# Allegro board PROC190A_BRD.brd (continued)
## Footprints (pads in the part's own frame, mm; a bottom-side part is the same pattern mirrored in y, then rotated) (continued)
CON_MUSBB5_629105150521_S_R_S_2-7
  round 0.686 hole 0.813 unplated: (-2.5,1.848) (2.5,1.848)
  rect 0.457x1.295 smd: 1(-1.3,2.948) 2(-0.65,2.948) 3(0,2.948) 4(0.65,2.948) 5(1.3,2.948)
  oval 1.448x2.311 hole 0.864x1.727: 6(-3.725,2.898) 7(3.725,2.898)
  oval 1.143x1.803 hole 0.559x1.219: 8(-3.875,-0.902) 9(3.875,-0.902)
CON_SD9_MEM2052-00-195-00_S_R_S_2
  rect 0.787x1.499 smd: 1(1.94,-3.66) 2(0.84,-3.26) 3(-0.26,-3.66) 4(-1.36,-3.86) 5(-2.46,-3.66) 6(-3.56,-3.86) 7(-4.66,-3.66) 8(-5.76,-3.66)
  rect 0.991x0.94 smd: 9(-3.56,7.425)
  rect 1.397x1.905 smd: SH1(6.6,-6.95) SH2(-6.55,-5.95)
  rect 1.295x1.397 smd: SH3(0.75,7.2)
  rect 1.194x1.397 smd: SH4(-5.008,7.2)
CON_USBC24_2012670_S_R_S_3-9
  rect 0.305x0.762 smd: A1(-3,4.056) A2(-2.5,4.056) A3(-2,4.056) A4(-1.5,4.056) A5(-1,4.056) A6(-0.5,4.056) A7(0.5,4.056) A8(1,4.056) A9(1.5,4.056) A10(2,4.056) A11(2.5,4.056) A12(3,4.056) B2(2.25,2.356) B3(1.75,2.356) B4(1.25,2.356) B5(0.75,2.356) B6(0.25,2.356) B7(-0.25,2.356) B8(-0.75,2.356) B9(-1.25,2.356) B10(-1.75,2.356) B11(-2.25,2.356)
  rect 0.94x0.762 smd: B1(3.05,2.356) B12(-3.05,2.356)
  oval 1.194x2.21 hole 0.61x1.575: SH1(-4.32,3.246) SH2(4.32,3.246)
  oval 1.194x3.708 hole 0.61x2.083: SH3(4.62,-2.114) SH4(-4.62,-2.114)
DIO_DFN0201_0-4
  rect 0.229x0.381 smd: 1(-0.22,0) 2(0.22,0)
DIO_DFN0402_0-5
  rect 0.356x0.61 smd: 1(-0.34,0) 2(0.34,0)
DIO_SOT23_123
  rect 1.016x0.61 smd: 1(-1.15,0.95) 2(-1.15,-0.95) 3(1.15,0)
DIO_SOT323-3_1-1
  rect 0.838x0.457 smd: 1(-1.05,0.65) 2(-1.05,-0.65) 3(1.05,0)
DSBGA12_15-74_60X70_0-4
  round 0.279 smd: A1(-0.4,0.6) A2(0,0.6) A3(0.4,0.6) B1(-0.4,0.2) B2(0,0.2) B3(0.4,0.2) C1(-0.4,-0.2) C2(0,-0.2) C3(0.4,-0.2) D1(-0.4,-0.6) D2(0,-0.6) D3(0.4,-0.6)
EMIFIL_BLM15A_0402_0-6
  rect 0.61x0.61 smd: 1(-0.46,0) 2(0.46,0)
EMIFIL_BLM18K_0603
  rect 0.94x1.194 smd: 1(-0.825,0) 2(0.825,0)
EMIFIL_BLM18P_0603_0-8
  rect 0.991x0.991 smd: 1(-0.75,0) 2(0.75,0)
HDR_1X2_90120-0122_S_T_5-6
  rect 1.702x1.702 hole 1.016: 1(0,0)
  round 1.702 hole 1.016: 2(-2.54,0)
HDR_1X2_61300211121_S_T_8-6
  rect 1.803x1.803 hole 1.118: 1(0,0)
  round 1.803 hole 1.118: 2(-2.54,0)
HDR_1X3_100_S_T
  rect 1.803x1.803 hole 1.118: 1(0,0)
  round 1.803 hole 1.118: 2(-2.54,0) 3(-5.08,0)
HDR_1X3_87224-3_S_T_10-8
  rect 1.6x1.6 hole 0.914: 1(0,0)
  round 1.6 hole 0.914: 2(-2.54,0) 3(-5.08,0)
HDR_2X4_90131-07_S_T_9-5
  rect 1.702x1.702 hole 1.016: 1(0,0)
  round 1.702 hole 1.016: 2(0,2.54) 3(2.54,0) 4(2.54,2.54) 5(5.08,0) 6(5.08,2.54) 7(7.62,0) 8(7.62,2.54)
HDR_2X5_PEC05DAAN_S_T_8-6
  rect 1.702x1.702 hole 1.016: 1(0,0)
  round 1.702 hole 1.016: 2(0,2.54) 3(2.54,0) 4(2.54,2.54) 5(5.08,0) 6(5.08,2.54) 7(7.62,0) 8(7.62,2.54) 9(10.16,0) 10(10.16,2.54)
HDR_2X10_FTR-110-51-D-06_S_S_8-7
  rect 0.711x3.124 smd: 1(-5.715,-2.578) 2(-5.715,2.578) 3(-4.445,-2.578) 4(-4.445,2.578) 5(-3.175,-2.578) 7(-1.905,-2.578) 8(-1.905,2.578) 9(-0.635,-2.578) 10(-0.635,2.578) 11(0.635,-2.578) 12(0.635,2.578) 13(1.905,-2.578) 14(1.905,2.578) 15(3.175,-2.578) 16(3.175,2.578) 17(4.445,-2.578) 18(4.445,2.578) 19(5.715,-2.578) 20(5.715,2.578)
HDR_6X2_61301221121_P_S_T_8-6
  rect 1.803x1.803 hole 1.118: 1(0,0)
  round 1.803 hole 1.118: 2(0,2.54) 3(2.54,0) 4(2.54,2.54) 5(5.08,0) 6(5.08,2.54) 7(7.62,0) 8(7.62,2.54) 9(10.16,0) 10(10.16,2.54) 11(12.7,0) 12(12.7,2.54)
IND4_DLW21H_90X60_SMD_1-4
  rect 0.889x0.356 smd: 1(-0.85,-0.425) 2(0.85,-0.425) 3(0.85,0.425) 4(-0.85,0.425)
IND0806
  rect 1.219x1.803 smd: 1(-0.85,0) 2(0.85,0)
IND0806_1-2
  rect 1.219x1.803 smd: 1(-0.85,0) 2(0.85,0)
IND1210_1-2
  rect 1.346x2.794 smd: 1(-1.6,0) 2(1.6,0)
IND_XAL8080_330X350_SMD_8
  rect 1.778x7.01 smd: 1(-2.58,0) 2(2.58,0)
LED_150040GS73220_40X20_SMD_0-4
  rect 0.406x0.457 smd: 1(-0.5,0) 2(0.5,0)
LED_150080VS75000_80X50_SMD_0-8
  rect 1.092x1.194 smd: 1(-1.05,0) 2(1.05,0)
LED_150080VS75000_80X50_SMD_0-8#2
  rect 1.092x1.194 smd: 1(-1.05,0) 2(1.05,0)
LQFP64_19-68_390X390_1-6
  rect 1.499x0.305 smd: 1(-5.7,3.75) 2(-5.7,3.25) 3(-5.7,2.75) 4(-5.7,2.25) 5(-5.7,1.75) 6(-5.7,1.25) 7(-5.7,0.75) 8(-5.7,0.25) 9(-5.7,-0.25) 10(-5.7,-0.75) 11(-5.7,-1.25) 12(-5.7,-1.75) 13(-5.7,-2.25) 14(-5.7,-2.75) 15(-5.7,-3.25) 16(-5.7,-3.75) 33(5.7,-3.75) 34(5.7,-3.25) 35(5.7,-2.75) 36(5.7,-2.25) 37(5.7,-1.75) 38(5.7,-1.25) 39(5.7,-0.75) 40(5.7,-0.25) 41(5.7,0.25) 42(5.7,0.75) 43(5.7,1.25) 44(5.7,1.75) 45(5.7,2.25) 46(5.7,2.75) 47(5.7,3.25) 48(5.7,3.75)
  rect 0.305x1.499 smd: 17(-3.75,-5.7) 18(-3.25,-5.7) 19(-2.75,-5.7) 20(-2.25,-5.7) 21(-1.75,-5.7) 22(-1.25,-5.7) 23(-0.75,-5.7) 24(-0.25,-5.7) 25(0.25,-5.7) 26(0.75,-5.7) 27(1.25,-5.7) 28(1.75,-5.7) 29(2.25,-5.7) 30(2.75,-5.7) 31(3.25,-5.7) 32(3.75,-5.7) 49(3.75,5.7) 50(3.25,5.7) 51(2.75,5.7) 52(2.25,5.7) 53(1.75,5.7) 54(1.25,5.7) 55(0.75,5.7) 56(0.25,5.7) 57(-0.25,5.7) 58(-0.75,5.7) 59(-1.25,5.7) 60(-1.75,5.7) 61(-2.25,5.7) 62(-2.75,5.7) 63(-3.25,5.7) 64(-3.75,5.7)
MSOP8_25-59_125X125_1-1
  rect 1.448x0.457 smd: 1(-2.2,0.975) 2(-2.2,0.325) 3(-2.2,-0.325) 4(-2.2,-0.975) 5(2.2,-0.975) 6(2.2,-0.325) 7(2.2,0.325) 8(2.2,0.975)
MSOP10_19-68_120X120_1-1
  rect 1.448x0.305 smd: 1(-2.2,1) 2(-2.2,0.5) 3(-2.2,0) 4(-2.2,-0.5) 5(-2.2,-1) 6(2.2,-1) 7(2.2,-0.5) 8(2.2,0) 9(2.2,0.5) 10(2.2,1)
QFN24_19-68_220X140_1
  rect 0.838x0.279 smd: 1(-2.725,-0.75) 12(2.725,-0.75) 13(2.725,0.75) 24(-2.725,0.75)
  rect 0.279x0.838 smd: 2(-2.25,-1.725) 3(-1.75,-1.725) 4(-1.25,-1.725) 5(-0.75,-1.725) 6(-0.25,-1.725) 7(0.25,-1.725) 8(0.75,-1.725) 9(1.25,-1.725) 10(1.75,-1.725) 11(2.25,-1.725) 14(2.25,1.725) 15(1.75,1.725) 16(1.25,1.725) 17(0.75,1.725) 18(0.25,1.725) 19(-0.25,1.725) 20(-0.75,1.725) 21(-1.25,1.725) 22(-1.75,1.725) 23(-2.25,1.725)
  custom 0.508x0.508 smd: 25(0,0)
QFN24_TAD5212IRGER_160X160_1
  rect 0.787x0.305 smd: 1(-2,1.25) 2(-2,0.75) 3(-2,0.25) 4(-2,-0.25) 5(-2,-0.75) 6(-2,-1.25) 13(2,-1.25) 14(2,-0.75) 15(2,-0.25) 16(2,0.25) 17(2,0.75) 18(2,1.25)
  rect 0.305x0.787 smd: 7(-1.25,-2) 8(-0.75,-2) 9(-0.25,-2) 10(0.25,-2) 11(0.75,-2) 12(1.25,-2) 19(1.25,2) 20(0.75,2) 21(0.25,2) 22(-0.25,2) 23(-0.75,2) 24(-1.25,2)
  rect 2.21x2.21 smd: 25(0,0)
  rect 0.254x0.254 smd: A1(-1.725,1.725) A2(-1.725,-1.725) A3(1.725,-1.725) A4(1.725,1.725)
QFN32_19-68_200X200
  rect 0.838x0.305 smd: 1(-2.5,1.75) 2(-2.5,1.25) 3(-2.5,0.75) 4(-2.5,0.25) 5(-2.5,-0.25) 6(-2.5,-0.75) 7(-2.5,-1.25) 8(-2.5,-1.75) 17(2.5,-1.75) 18(2.5,-1.25) 19(2.5,-0.75) 20(2.5,-0.25) 21(2.5,0.25) 22(2.5,0.75) 23(2.5,1.25) 24(2.5,1.75)
  rect 0.305x0.838 smd: 9(-1.75,-2.5) 10(-1.25,-2.5) 11(-0.75,-2.5) 12(-0.25,-2.5) 13(0.25,-2.5) 14(0.75,-2.5) 15(1.25,-2.5) 16(1.75,-2.5) 25(1.75,2.5) 26(1.25,2.5) 27(0.75,2.5) 28(0.25,2.5) 29(-0.25,2.5) 30(-0.75,2.5) 31(-1.25,2.5) 32(-1.75,2.5)
  rect 3.556x3.556 smd: 33(0,0)
QFN32_19-68_200X200_0-8_EP3-6
  rect 0.787x0.305 smd: 1(-2.5,1.75) 2(-2.5,1.25) 3(-2.5,0.75) 4(-2.5,0.25) 5(-2.5,-0.25) 6(-2.5,-0.75) 7(-2.5,-1.25) 8(-2.5,-1.75) 17(2.5,-1.75) 18(2.5,-1.25) 19(2.5,-0.75) 20(2.5,-0.25) 21(2.5,0.25) 22(2.5,0.75) 23(2.5,1.25) 24(2.5,1.75)
  rect 0.305x0.787 smd: 9(-1.75,-2.5) 10(-1.25,-2.5) 11(-0.75,-2.5) 12(-0.25,-2.5) 13(0.25,-2.5) 14(0.75,-2.5) 15(1.25,-2.5) 16(1.75,-2.5) 25(1.75,2.5) 26(1.25,2.5) 27(0.75,2.5) 28(0.25,2.5) 29(-0.25,2.5) 30(-0.75,2.5) 31(-1.25,2.5) 32(-1.75,2.5)
  rect 3.607x3.607 smd: 33(0,0)
RES0201_0-5
  rect 0.356x0.33 smd: 1(-0.28,0) 2(0.28,0)
RES0402_0-5
  rect 0.559x0.635 smd: 1(-0.49,0) 2(0.49,0)
RES0603_0-5
  rect 0.635x0.991 smd: 1(-0.74,0) 2(0.74,0)
RES0603_0-75
  rect 0.635x0.991 smd: 1(-0.74,0) 2(0.74,0)
RES0805_0-75
  rect 1.194x1.448 smd: 1(-0.95,0) 2(0.95,0)
RES_CST0612_0612-4_0-9
  rect 0.991x2.311 smd: 1(-0.85,0.6) 4(0.85,0.6)
  rect 0.991x0.787 smd: 2(-0.85,-1.35) 3(0.85,-1.35)
RES_KRL3216T4_1206-4_0-7
  rect 1.143x0.356 smd: 1(-0.775,1.5) 4(0.775,1.5)
  rect 1.143x2.692 smd: 2(-0.775,-0.325) 3(0.775,-0.325)
RESA_EXB_0201-4_0-5
  rect 0.203x0.305 smd: 1(-0.6,-0.275) 2(-0.2,-0.275) 3(0.2,-0.275) 4(0.6,-0.275) 5(0.6,0.275) 6(0.2,0.275) 7(-0.2,0.275) 8(-0.6,0.275)
SC70-5
  rect 0.94x0.406 smd: 1(-1.1,0.65) 2(-1.1,0) 3(-1.1,-0.65) 4(1.1,-0.65) 5(1.1,0.65)
SC70-5_1-1
  rect 0.762x0.406 smd: 1(-1,0.65) 2(-1,0) 3(-1,-0.65) 4(1,-0.65) 5(1,0.65)
SC70-5_1-1#2
  rect 0.94x0.406 smd: 1(-1.1,0.65) 2(-1.1,0) 3(-1.1,-0.65) 4(1.1,-0.65) 5(1.1,0.65)
SC70-6_1-1
  rect 0.762x0.406 smd: 1(-1,0.65) 2(-1,0) 3(-1,-0.65) 4(1,-0.65) 5(1,0) 6(1,0.65)
SOIC8_1-8
  rect 1.549x0.61 smd: 1(-2.7,1.905) 2(-2.7,0.635) 3(-2.7,-0.635) 4(-2.7,-1.905) 5(2.7,-1.905) 6(2.7,-0.635) 7(2.7,0.635) 8(2.7,1.905)
SON6_19-68_40X60_PB_0-6
  rect 0.356x0.305 smd: 1(-0.3,0.5) 2(-0.3,0) 3(-0.3,-0.5) 4(0.3,-0.5) 5(0.3,0) 6(0.3,0.5)
SON6_25-59_85X85
  rect 0.61x0.356 smd: 1(-1.05,0.65) 2(-1.05,0) 3(-1.05,-0.65) 4(1.05,-0.65) 5(1.05,0) 6(1.05,0.65)
  rect 1.092x1.702 smd: 7(0,0)
SON6_25-59_85X85_0-8
  rect 0.61x0.356 smd: 1(-1.05,0.65) 2(-1.05,0) 3(-1.05,-0.65) 4(1.05,-0.65) 5(1.05,0) 6(1.05,0.65)
  rect 1.067x1.702 smd: 7(0,0)
SON6_25-59_85X85_0-8#2
  rect 0.61x0.356 smd: 1(-1.05,0.65) 2(-1.05,0) 3(-1.05,-0.65) 4(1.05,-0.65) 5(1.05,0) 6(1.05,0.65)
  rect 1.067x1.702 smd: 7(0,0)
SON6_CSD17313Q2_80X80
  rect 0.406x0.457 smd: 1(-0.65,-0.923) 2(0,-0.923) 3(0.65,-0.923) 4(0.65,0.923) 5(0,0.923) 6(-0.65,0.923)
  rect 0.406x0.864 smd: 7(0.65,0.096)
  rect 1.041x1.092 smd: 8(-0.325,0)
SON6_SN74LVC2G17_40X60_0-6
  rect 0.356x0.203 smd: 1(-0.275,0.5)
  rect 0.305x0.203 smd: 2(-0.3,0) 3(-0.3,-0.5) 4(0.3,-0.5) 5(0.3,0) 6(0.3,0.5)
SON8_25-59_130X130_1
  rect 0.762x0.356 smd: 1(-1.45,0.975) 2(-1.45,0.325) 3(-1.45,-0.325) 4(-1.45,-0.975) 5(1.45,-0.975) 6(1.45,-0.325) 7(1.45,0.325) 8(1.45,0.975)
  rect 1.753x2.515 smd: 9(0,0)
SOT23-5
  rect 0.889x0.559 smd: 1(-1.2,0.95) 2(-1.2,0) 3(-1.2,-0.95) 4(1.2,-0.95) 5(1.2,0.95)
SOT23-5#2
  rect 1.092x0.61 smd: 1(-1.3,0.95) 2(-1.3,0) 3(-1.3,-0.95) 4(1.3,-0.95) 5(1.3,0.95)
SOT23-5_1-5
  rect 1.092x0.61 smd: 1(-1.3,0.95) 2(-1.3,0) 3(-1.3,-0.95) 4(1.3,-0.95) 5(1.3,0.95)
SOT23-6
  rect 1.041x0.61 smd: 1(-1.35,0.95) 2(-1.35,0) 3(-1.35,-0.95) 4(1.35,-0.95) 5(1.35,0) 6(1.35,0.95)
SOT23-14_1-1
  rect 1.041x0.305 smd: 1(-1.5,1.5) 2(-1.5,1) 3(-1.5,0.5) 4(-1.5,0) 5(-1.5,-0.5) 6(-1.5,-1) 7(-1.5,-1.5) 8(1.5,-1.5) 9(1.5,-1) 10(1.5,-0.5) 11(1.5,0) 12(1.5,0.5) 13(1.5,1) 14(1.5,1.5)
SOT23-123_1-2
  rect 1.016x0.61 smd: 1(-1.15,0.95) 2(-1.15,-0.95) 3(1.15,0)
SOT553-5_0-6
  rect 0.559x0.229 smd: 1(-0.69,0.5) 2(-0.69,0) 3(-0.69,-0.5) 4(0.69,-0.5) 5(0.69,0.5)
SW3_CAS-120TA_215X100_SMD
  rect 1.6x1.016 smd: 1(-1.75,-1.15) 2(0,1.15) 3(1.75,-1.15)
SW4_49-99_150X230_SMD_2-7
  rect 0.762x1.27 smd: 1(-0.635,-3.81) 2(0.635,-3.81) 3(0.635,3.81) 4(-0.635,3.81)
SW4_100X216_200X200_SMD_4-2
  rect 1.27x1.27 smd: 1(-1.27,-2.75) 2(1.27,-2.75) 3(1.27,2.75) 4(-1.27,2.75)
SW4_100X216_200X200_SMD_4-2#2
  rect 1.27x1.27 smd: 1(-1.27,-2.75) 2(1.27,-2.75) 3(1.27,2.75) 4(-1.27,2.75)
SW16_416131160808_460X230_SMD_2-7
  rect 0.762x1.27 smd: 1(-4.445,-3.81) 2(-3.175,-3.81) 3(-1.905,-3.81) 4(-0.635,-3.81) 5(0.635,-3.81) 6(1.905,-3.81) 7(3.175,-3.81) 8(4.445,-3.81) 9(4.445,3.81) 10(3.175,3.81) 11(1.905,3.81) 12(0.635,3.81) 13(-0.635,3.81) 14(-1.905,3.81) 15(-3.175,3.81) 16(-4.445,3.81)
SW_TDA01H0S_240X90_SMD_2-3
  rect 1.27x0.762 smd: 1(-3.81,0) 2(3.81,0)
TO_SOT23-123
  rect 1.016x1.397 smd: 1(-0.95,-1.1) 2(0.95,-1.1) 3(0,1.1)
TP20_SMD
  round 0.508 smd: 1(0,0)
TP30_SMD
  round 0.762 smd: 1(0,0)
TP40_SMD
  round 1.016 smd: 1(0,0)
TP_40X65
  round 1.651 hole 1.016: 1(0,0)
TQFN42_19-68_140X360_0-8
  rect 0.813x0.305 smd: 1(-1.7,4) 2(-1.7,3.5) 3(-1.7,3) 4(-1.7,2.5) 5(-1.7,2) 6(-1.7,1.5) 7(-1.7,1) 8(-1.7,0.5) 9(-1.7,0) 10(-1.7,-0.5) 11(-1.7,-1) 12(-1.7,-1.5) 13(-1.7,-2) 14(-1.7,-2.5) 15(-1.7,-3) 16(-1.7,-3.5) 17(-1.7,-4) 22(1.7,-4) 23(1.7,-3.5) 24(1.7,-3) 25(1.7,-2.5) 26(1.7,-2) 27(1.7,-1.5) 28(1.7,-1) 29(1.7,-0.5) 30(1.7,0) 31(1.7,0.5) 32(1.7,1) 33(1.7,1.5) 34(1.7,2) 35(1.7,2.5) 36(1.7,3) 37(1.7,3.5) 38(1.7,4)
  rect 0.305x0.813 smd: 18(-0.75,-4.45) 19(-0.25,-4.45) 20(0.25,-4.45) 21(0.75,-4.45) 39(0.75,4.45) 40(0.25,4.45) 41(-0.25,4.45) 42(-0.75,4.45)
  rect 2.159x7.645 smd: 43(0,0)
TQFP128_15-74_550X550_1-2
  rect 1.499x0.203 smd: 1(-7.7,6.2) 2(-7.7,5.8) 3(-7.7,5.4) 4(-7.7,5) 5(-7.7,4.6) 6(-7.7,4.2) 7(-7.7,3.8) 8(-7.7,3.4) 9(-7.7,3) 10(-7.7,2.6) 11(-7.7,2.2) 12(-7.7,1.8) 13(-7.7,1.4) 14(-7.7,1) 15(-7.7,0.6) 16(-7.7,0.2) 17(-7.7,-0.2) 18(-7.7,-0.6) 19(-7.7,-1) 20(-7.7,-1.4) 21(-7.7,-1.8) 22(-7.7,-2.2) 23(-7.7,-2.6) 24(-7.7,-3) 25(-7.7,-3.4) 26(-7.7,-3.8) 27(-7.7,-4.2) 28(-7.7,-4.6) 29(-7.7,-5) 30(-7.7,-5.4) 31(-7.7,-5.8) 32(-7.7,-6.2) 65(7.7,-6.2) 66(7.7,-5.8) 67(7.7,-5.4) 68(7.7,-5) 69(7.7,-4.6) 70(7.7,-4.2) 71(7.7,-3.8) 72(7.7,-3.4) 73(7.7,-3) 74(7.7,-2.6) 75(7.7,-2.2) 76(7.7,-1.8) 77(7.7,-1.4) 78(7.7,-1) 79(7.7,-0.6) 80(7.7,-0.2) 81(7.7,0.2) 82(7.7,0.6) 83(7.7,1) 84(7.7,1.4) 85(7.7,1.8) 86(7.7,2.2) 87(7.7,2.6) 88(7.7,3) 89(7.7,3.4) 90(7.7,3.8) 91(7.7,4.2) 92(7.7,4.6) 93(7.7,5) 94(7.7,5.4) 95(7.7,5.8) 96(7.7,6.2)
  rect 0.203x1.499 smd: 33(-6.2,-7.7) 34(-5.8,-7.7) 35(-5.4,-7.7) 36(-5,-7.7) 37(-4.6,-7.7) 38(-4.2,-7.7) 39(-3.8,-7.7) 40(-3.4,-7.7) 41(-3,-7.7) 42(-2.6,-7.7) 43(-2.2,-7.7) 44(-1.8,-7.7) 45(-1.4,-7.7) 46(-1,-7.7) 47(-0.6,-7.7) 48(-0.2,-7.7) 49(0.2,-7.7) 50(0.6,-7.7) 51(1,-7.7) 52(1.4,-7.7) 53(1.8,-7.7) 54(2.2,-7.7) 55(2.6,-7.7) 56(3,-7.7) 57(3.4,-7.7) 58(3.8,-7.7) 59(4.2,-7.7) 60(4.6,-7.7) 61(5,-7.7) 62(5.4,-7.7) 63(5.8,-7.7) 64(6.2,-7.7) 97(6.2,7.7) 98(5.8,7.7) 99(5.4,7.7) 100(5,7.7) 101(4.6,7.7) 102(4.2,7.7) 103(3.8,7.7) 104(3.4,7.7) 105(3,7.7) 106(2.6,7.7) 107(2.2,7.7) 108(1.8,7.7) 109(1.4,7.7) 110(1,7.7) 111(0.6,7.7) 112(0.2,7.7) 113(-0.2,7.7) 114(-0.6,7.7) 115(-1,7.7) 116(-1.4,7.7) 117(-1.8,7.7) 118(-2.2,7.7) 119(-2.6,7.7) 120(-3,7.7) 121(-3.4,7.7) 122(-3.8,7.7) 123(-4.2,7.7) 124(-4.6,7.7) 125(-5,7.7) 126(-5.4,7.7) 127(-5.8,7.7) 128(-6.2,7.7)
TSSOP8_25-59_125X180_1-2
  rect 1.499x0.457 smd: 1(-2.9,0.975) 2(-2.9,0.325) 3(-2.9,-0.325) 4(-2.9,-0.975) 5(2.9,-0.975) 6(2.9,-0.325) 7(2.9,0.325) 8(2.9,0.975)
TSSOP14_25-59_205X180_1-2
  rect 1.499x0.457 smd: 1(-2.9,1.95) 2(-2.9,1.3) 3(-2.9,0.65) 4(-2.9,0) 5(-2.9,-0.65) 6(-2.9,-1.3) 7(-2.9,-1.95) 8(2.9,-1.95) 9(2.9,-1.3) 10(2.9,-0.65) 11(2.9,0) 12(2.9,0.65) 13(2.9,1.3) 14(2.9,1.95)
TSSOP20_25-59_260X180
  rect 1.499x0.457 smd: 1(-2.9,2.925) 2(-2.9,2.275) 3(-2.9,1.625) 4(-2.9,0.975) 5(-2.9,0.325) 6(-2.9,-0.325) 7(-2.9,-0.975) 8(-2.9,-1.625) 9(-2.9,-2.275) 10(-2.9,-2.925) 11(2.9,-2.925) 12(2.9,-2.275) 13(2.9,-1.625) 14(2.9,-0.975) 15(2.9,-0.325) 16(2.9,0.325) 17(2.9,0.975) 18(2.9,1.625) 19(2.9,2.275) 20(2.9,2.925)
TSSOP56_19-68_560X240_1-2
  rect 1.499x0.305 smd: 1(-3.75,6.75) 2(-3.75,6.25) 3(-3.75,5.75) 4(-3.75,5.25) 5(-3.75,4.75) 6(-3.75,4.25) 7(-3.75,3.75) 8(-3.75,3.25) 9(-3.75,2.75) 10(-3.75,2.25) 11(-3.75,1.75) 12(-3.75,1.25) 13(-3.75,0.75) 14(-3.75,0.25) 15(-3.75,-0.25) 16(-3.75,-0.75) 17(-3.75,-1.25) 18(-3.75,-1.75) 19(-3.75,-2.25) 20(-3.75,-2.75) 21(-3.75,-3.25) 22(-3.75,-3.75) 23(-3.75,-4.25) 24(-3.75,-4.75) 25(-3.75,-5.25) 26(-3.75,-5.75) 27(-3.75,-6.25) 28(-3.75,-6.75) 29(3.75,-6.75) 30(3.75,-6.25) 31(3.75,-5.75) 32(3.75,-5.25) 33(3.75,-4.75) 34(3.75,-4.25) 35(3.75,-3.75) 36(3.75,-3.25) 37(3.75,-2.75) 38(3.75,-2.25) 39(3.75,-1.75) 40(3.75,-1.25) 41(3.75,-0.75) 42(3.75,-0.25) 43(3.75,0.25) 44(3.75,0.75) 45(3.75,1.25) 46(3.75,1.75) 47(3.75,2.25) 48(3.75,2.75) 49(3.75,3.25) 50(3.75,3.75) 51(3.75,4.25) 52(3.75,4.75) 53(3.75,5.25) 54(3.75,5.75) 55(3.75,6.25) 56(3.75,6.75)
TVSOP14_15-74_180X150_1-2
  rect 1.499x0.203 smd: 1(-2.9,1.2) 2(-2.9,0.8) 3(-2.9,0.4) 4(-2.9,0) 5(-2.9,-0.4) 6(-2.9,-0.8) 7(-2.9,-1.2) 8(2.9,-1.2) 9(2.9,-0.8) 10(2.9,-0.4) 11(2.9,0) 12(2.9,0.4) 13(2.9,0.8) 14(2.9,1.2)
unnamed
  round 0.686 hole 0.813 unplated: (-1.27,1.076) (0,1.076) (1.27,1.076)
unnamed#2
  round 1.016 smd: (0,0)
UQFN10_19-68_80X60_0-6
  rect 0.584x0.305 smd: 1(-0.635,0.75) 4(-0.635,-0.75) 6(0.635,-0.75) 9(0.635,0.75)
  rect 0.584x0.254 smd: 2(-0.635,0.25) 3(-0.635,-0.25) 7(0.635,-0.25) 8(0.635,0.25)
  rect 0.305x0.635 smd: 5(0,-0.86) 10(0,0.86)
UQFN16_TMUX1574_70X100_0-6
  rect 0.711x0.203 smd: 1(-0.75,0.6)
  rect 0.61x0.203 smd: 2(-0.8,0.2) 3(-0.8,-0.2) 4(-0.8,-0.6) 9(0.8,-0.6) 10(0.8,-0.2) 11(0.8,0.2) 12(0.8,0.6)
  rect 0.203x0.61 smd: 5(-0.6,-1.2) 6(-0.2,-1.2) 7(0.2,-1.2) 8(0.6,-1.2) 13(0.6,1.2) 14(0.2,1.2) 15(-0.2,1.2) 16(-0.6,1.2)
UQFN16_TMUX1574_70X100_0-6#2
  rect 0.711x0.203 smd: 1(-0.75,0.6)
  rect 0.61x0.203 smd: 2(-0.8,0.2) 3(-0.8,-0.2) 4(-0.8,-0.6) 9(0.8,-0.6) 10(0.8,-0.2) 11(0.8,0.2) 12(0.8,0.6)
  rect 0.203x0.61 smd: 5(-0.6,-1.2) 6(-0.2,-1.2) 7(0.2,-1.2) 8(0.6,-1.2) 13(0.6,1.2) 14(0.2,1.2) 15(-0.2,1.2) 16(-0.6,1.2)
USON10_TMUX1204_40X100_0-6
  rect 0.559x0.203 smd: 1(-0.417,1) 2(-0.417,0.5) 4(-0.417,-0.5) 5(-0.417,-1) 6(0.417,-1) 7(0.417,-0.5) 9(0.417,0.5) 10(0.417,1)
  rect 0.559x0.406 smd: 3(-0.417,0) 8(0.417,0)
USON10_TPD4E05U_40X100_0-6
  rect 0.559x0.305 smd: 1(-0.385,1) 2(-0.385,0.5) 4(-0.385,-0.5) 5(-0.385,-1) 6(0.385,-1) 7(0.385,-0.5) 9(0.385,0.5) 10(0.385,1)
  rect 0.559x0.406 smd: 3(-0.385,0) 8(0.385,0)
VFBGA153_19-68_460X520_1-3
  round 0.254 smd: A1(-3.25,3.25) A2(-2.75,3.25) A3(-2.25,3.25) A4(-1.75,3.25) A5(-1.25,3.25) A6(-0.75,3.25) A7(-0.25,3.25) A8(0.25,3.25) A9(0.75,3.25) A10(1.25,3.25) A11(1.75,3.25) A12(2.25,3.25) A13(2.75,3.25) A14(3.25,3.25) B1(-3.25,2.75) B2(-2.75,2.75) B3(-2.25,2.75) B4(-1.75,2.75) B5(-1.25,2.75) B6(-0.75,2.75) B7(-0.25,2.75) B8(0.25,2.75) B9(0.75,2.75) B10(1.25,2.75) B11(1.75,2.75) B12(2.25,2.75) B13(2.75,2.75) B14(3.25,2.75) C1(-3.25,2.25) C2(-2.75,2.25) C3(-2.25,2.25) C4(-1.75,2.25) C5(-1.25,2.25) C6(-0.75,2.25) C7(-0.25,2.25) C8(0.25,2.25) C9(0.75,2.25) C10(1.25,2.25) C11(1.75,2.25) C12(2.25,2.25) C13(2.75,2.25) C14(3.25,2.25) D1(-3.25,1.75) D2(-2.75,1.75) D3(-2.25,1.75) D4(-1.75,1.75) D12(2.25,1.75) D13(2.75,1.75) D14(3.25,1.75) E1(-3.25,1.25) E2(-2.75,1.25) E3(-2.25,1.25) E5(-1.25,1.25) E6(-0.75,1.25) E7(-0.25,1.25) E8(0.25,1.25) E9(0.75,1.25) E10(1.25,1.25) E12(2.25,1.25) E13(2.75,1.25) E14(3.25,1.25) F1(-3.25,0.75) F2(-2.75,0.75) F3(-2.25,0.75) F5(-1.25,0.75) F10(1.25,0.75) F12(2.25,0.75) F13(2.75,0.75) F14(3.25,0.75) G1(-3.25,0.25) G2(-2.75,0.25) G3(-2.25,0.25) G5(-1.25,0.25) G10(1.25,0.25) G12(2.25,0.25) G13(2.75,0.25) G14(3.25,0.25) H1(-3.25,-0.25) H2(-2.75,-0.25) H3(-2.25,-0.25) H5(-1.25,-0.25) H10(1.25,-0.25) H12(2.25,-0.25) H13(2.75,-0.25) H14(3.25,-0.25) J1(-3.25,-0.75) J2(-2.75,-0.75) J3(-2.25,-0.75) J5(-1.25,-0.75) J10(1.25,-0.75) J12(2.25,-0.75) J13(2.75,-0.75) J14(3.25,-0.75) K1(-3.25,-1.25) K2(-2.75,-1.25) K3(-2.25,-1.25) K5(-1.25,-1.25) K6(-0.75,-1.25) K7(-0.25,-1.25) K8(0.25,-1.25) K9(0.75,-1.25) K10(1.25,-1.25) K12(2.25,-1.25) K13(2.75,-1.25) K14(3.25,-1.25) L1(-3.25,-1.75) L2(-2.75,-1.75) L3(-2.25,-1.75) L12(2.25,-1.75) L13(2.75,-1.75) L14(3.25,-1.75) M1(-3.25,-2.25) M2(-2.75,-2.25) M3(-2.25,-2.25) M4(-1.75,-2.25) M5(-1.25,-2.25) M6(-0.75,-2.25) M7(-0.25,-2.25) M8(0.25,-2.25) M9(0.75,-2.25) M10(1.25,-2.25) M11(1.75,-2.25) M12(2.25,-2.25) M13(2.75,-2.25) M14(3.25,-2.25) N1(-3.25,-2.75) N2(-2.75,-2.75) N3(-2.25,-2.75) N4(-1.75,-2.75) N5(-1.25,-2.75) N6(-0.75,-2.75) N7(-0.25,-2.75) N8(0.25,-2.75) N9(0.75,-2.75) N10(1.25,-2.75) N11(1.75,-2.75) N12(2.25,-2.75) N13(2.75,-2.75) N14(3.25,-2.75) P1(-3.25,-3.25) P2(-2.75,-3.25) P3(-2.25,-3.25) P4(-1.75,-3.25) P5(-1.25,-3.25) P6(-0.75,-3.25) P7(-0.25,-3.25) P8(0.25,-3.25) P9(0.75,-3.25) P10(1.25,-3.25) P11(1.75,-3.25) P12(2.25,-3.25) P13(2.75,-3.25) P14(3.25,-3.25)
VQFN56_TPS65987D_280X280_1
  rect 0.813x0.711 smd: 1(-3.35,2.4) 3(-3.35,1.6) 11(-3.35,-1.6) 13(-3.35,-2.4)
  rect 0.711x0.203 smd: 5(-3.35,1) 6(-3.35,0.6) 7(-3.35,0.2) 8(-3.35,-0.2) 9(-3.35,-0.6) 10(-3.35,-1) 29(3.35,-2.6) 30(3.35,-2.2) 31(3.35,-1.8) 32(3.35,-1.4) 33(3.35,-1) 34(3.35,-0.6) 35(3.35,-0.2) 36(3.35,0.2) 37(3.35,0.6) 38(3.35,1) 39(3.35,1.4) 40(3.35,1.8) 41(3.35,2.2) 42(3.35,2.6)
  rect 0.203x0.711 smd: 15(-2.6,-3.35) 16(-2.2,-3.35) 17(-1.8,-3.35) 18(-1.4,-3.35) 19(-1,-3.35) 20(-0.6,-3.35) 21(-0.2,-3.35) 22(0.2,-3.35) 23(0.6,-3.35) 24(1,-3.35) 25(1.4,-3.35) 26(1.8,-3.35) 27(2.2,-3.35) 28(2.6,-3.35) 43(2.6,3.35) 44(2.2,3.35) 45(1.8,3.35) 46(1.4,3.35) 47(1,3.35) 48(0.6,3.35) 49(0.2,3.35) 50(-0.2,3.35) 51(-0.6,3.35) 52(-1,3.35) 53(-1.4,3.35) 54(-1.8,3.35) 55(-2.2,3.35) 56(-2.6,3.35)
  rect 1.753x2.591 smd: 57(-1.875,1.45)
  rect 1.753x2.54 smd: 58(-1.875,-1.475)
  rect 3.404x5.512 smd: 59(1.05,0)
VQFN-HR36-35_TPS65224_240X200_1
  custom 0.206x0.206 smd: 1(-2.5,2) 9(-2.5,-2) 19(2.5,-2) 27(2.5,2)
  rect 0.838x0.254 smd: 2(-2.775,1.5) 8(-2.775,-1.5) 20(2.775,-1.5) 26(2.775,1.5)
  rect 0.914x0.254 smd: 3(-2.738,1) 7(-2.738,-1) 21(2.738,-1) 25(2.738,1)
  rect 1.041x0.254 smd: 4(-2.675,0.5) 6(-2.675,-0.5) 22(2.675,-0.5) 24(2.675,0.5)
  custom 0.3x0.3 smd: 5(0,0)
  rect 0.254x0.838 smd: 10(-2,-2.275) 11(-1.5,-2.275) 17(1.5,-2.275) 18(2,-2.275) 28(2,2.275) 29(1.5,2.275) 35(-1.5,2.275) 36(-2,2.275)
  rect 0.254x0.914 smd: 12(-1,-2.237) 13(-0.5,-2.237) 15(0.5,-2.237) 16(1,-2.237) 30(1,2.237) 31(0.5,2.237) 33(-0.5,2.237) 34(-1,2.237)
  rect 0.254x1.702 smd: 14(0,-1.85) 32(0,1.85)
VQFNHR14_LM61460_160X140_1
  custom 0.175x0.175 smd: 1(-1.675,1.15) 5(-1.675,-1.15)
  rect 0.711x0.254 smd: 2(-1.85,0.525) 4(-1.85,-0.525)
  rect 0.711x0.305 smd: 3(-1.85,0)
  rect 0.254x0.711 smd: 6(-1.125,-1.6) 7(-0.625,-1.6) 13(-0.625,1.6) 14(-1.125,1.6)
  rect 0.406x0.991 smd: 8(0.45,-1.45) 12(0.45,1.45)
  custom 0.2x0.2 smd: 9(1.6,-1.15) 11(1.6,1.15)
  rect 2.388x0.406 smd: 10(1,0)
VSON4_LMK6CE_80X100_SMD_1
  rect 0.889x0.66 smd: 1(-0.749,0.826) 2(-0.749,-0.826) 3(0.749,-0.826) 4(0.749,0.826)
VSONHR6_TPS62826_60X60_1
  rect 0.711x0.356 smd: 1(-0.65,0.5) 2(-0.65,0) 3(-0.65,-0.5)
  rect 0.991x0.203 smd: 4(0.45,-0.5) 5(0.45,0) 6(0.45,0.5)
VSSOP8_19-68_85X95
  rect 0.813x0.305 smd: 1(-1.55,0.75) 2(-1.55,0.25) 3(-1.55,-0.25) 4(-1.55,-0.75) 5(1.55,-0.75) 6(1.55,-0.25) 7(1.55,0.25) 8(1.55,0.75)
VSSOP8_19-68_85X95_0-9
  rect 0.838x0.305 smd: 1(-1.55,0.75) 2(-1.55,0.25) 3(-1.55,-0.25) 4(-1.55,-0.75) 5(1.55,-0.75) 6(1.55,-0.25) 7(1.55,0.25) 8(1.55,0.75)
VSSOP8_19-68_85X95_0-9#2
  rect 0.838x0.305 smd: 1(-1.55,0.75) 2(-1.55,0.25) 3(-1.55,-0.25) 4(-1.55,-0.75) 5(1.55,-0.75) 6(1.55,-0.25) 7(1.55,0.25) 8(1.55,0.75)
WFQFN24_CDCE6214-Q1_160X160_0-9
  rect 0.61x0.254 smd: 1(-1.9,1.25) 2(-1.9,0.75) 3(-1.9,0.25) 4(-1.9,-0.25) 5(-1.9,-0.75) 6(-1.9,-1.25) 13(1.9,-1.25) 14(1.9,-0.75) 15(1.9,-0.25) 16(1.9,0.25) 17(1.9,0.75) 18(1.9,1.25)
  rect 0.254x0.61 smd: 7(-1.25,-1.9) 8(-0.75,-1.9) 9(-0.25,-1.9) 10(0.25,-1.9) 11(0.75,-1.9) 12(1.25,-1.9) 19(1.25,1.9) 20(0.75,1.9) 21(0.25,1.9) 22(-0.25,1.9) 23(-0.75,1.9) 24(-1.25,1.9)
  rect 2.794x2.794 smd: 25(0,0)
  rect 0.254x0.254 smd: A1(-1.75,1.75) A2(-1.75,-1.75) A3(1.75,-1.75) A4(1.75,1.75)
WQFN24_19-68_160X160
  rect 0.813x0.305 smd: 1(-2,1.25) 2(-2,0.75) 3(-2,0.25) 4(-2,-0.25) 5(-2,-0.75) 6(-2,-1.25) 13(2,-1.25) 14(2,-0.75) 15(2,-0.25) 16(2,0.25) 17(2,0.75) 18(2,1.25)
  rect 0.305x0.813 smd: 7(-1.25,-2) 8(-0.75,-2) 9(-0.25,-2) 10(0.25,-2) 11(0.75,-2) 12(1.25,-2) 19(1.25,2) 20(0.75,2) 21(0.25,2) 22(-0.25,2) 23(-0.75,2) 24(-1.25,2)
  rect 2.692x2.692 smd: 25(0,0)
WSON6_CSD13202Q2_80X80_0-8
  rect 0.457x0.305 smd: 1(-0.975,0.65) 2(-0.975,0) 3(-0.975,-0.65) 4(0.975,-0.65) 5(0.975,0) 6(0.975,0.65)
  rect 0.762x0.305 smd: 7(0.095,-0.65)
  rect 0.991x0.94 smd: 8(0,0.325)
X2SON3_ESD122DMX_30X40_0-4
  rect 0.203x0.203 smd: 1(-0.15,0) 2(0.15,-0.34) 3(0.15,0.34)
X2SON5_TLV7021_30X30_0-4
  custom 0.08x0.08 smd: 1(-0.39,0.24) 2(-0.39,-0.24) 4(0.39,-0.24) 5(0.39,0.24)
  rect 0.356x0.356 smd rot 45: 3(0,0)
X2SON8_15-74_70X50
  rect 0.838x0.203 smd: 1(-0.55,0.6) 2(-0.55,0.2) 3(-0.55,-0.2) 4(-0.55,-0.6) 5(0.55,-0.6) 6(0.55,-0.2) 7(0.55,0.2) 8(0.55,0.6)
X2SON8_TXS0102_40X60_0-4
  rect 0.61x0.178 smd: 1(-0.4,0.525)
  rect 0.508x0.178 smd: 2(-0.45,0.175) 3(-0.45,-0.175) 4(-0.45,-0.525) 5(0.45,-0.525) 6(0.45,-0.175) 7(0.45,0.175) 8(0.45,0.525)
XTAL4_ABM3B_210X130_SMD
  rect 1.803x1.219 smd: 1(-2,-1.2) 2(2,-1.2) 3(2,1.2) 4(-2,1.2)
XTAL4_ABMM_280X200_SMD_1-3
  rect 2.21x1.397 smd: 1(-3.15,-1.27) 2(-3.15,1.27) 3(3.15,1.27)
  rect 2.388x1.397 smd: 4(3.05,-1.27)
XTAL4_XRCGB-FM_80X60_SMD_0-7
  rect 0.762x0.711 smd: 1(-0.675,-0.5) 2(0.675,-0.5) 3(0.675,0.5) 4(-0.675,0.5)
XTAL_ABM3_205X130_SMD_1-4
  rect 1.803x2.413 smd: 1(-1.9,0) 2(1.9,0)
XTAL_ECS-32_130X60_SMD_0-9
  rect 1.118x1.905 smd: 1(-1.25,0) 2(1.25,0)

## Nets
AVDD_3V3_DAC: C29.1 C30.1 C31.1 C32.1 C349.1 C350.1 C351.1 C352.1 FL1.2 R28.2 R29.1 R33.1 R35.2 U5.23 U6.23 U76.23 U77.23
DGND: C1.2 C2.2 C3.2 C11.1 C13.1 C15.1 C17.1 C20.1 C21.1 C22.1 C23.1 C28.2 C29.2 C30.2 C31.2 C32.2 C33.1 C35.2 C37.2 C38.2 C42.2 C43.2 C45.2 C46.2 C47.2 C48.2 C49.2 C50.2 C51.2 C52.2 C53.1 C54.2 C55.2 C56.2 C57.2 C60.1 C61.2 C62.2 C63.2 C64.2 C65.2 C66.2 C67.2 C68.2 C69.2 C70.2 C71.2 C72.2 C73.2 C74.2 C75.2 C76.2 C77.2 C78.2 C81.2 C82.2 C84.2 C85.2 C86.2 C87.2 C88.1 C89.2 C90.2 C92.1 C93.1 C95.2 C96.2 C97.1 C98.2 C99.2 C100.2 C101.2 C102.1 C103.1 C104.1 C105.2 C107.2 C109.2 C121.2 C122.1 C126.1 C128.2 C129.2 C130.2 C133.2 C134.2 C135.2 C136.2 C137.2 C138.2 C140.2 C141.2 C142.2 C146.2 C147.2 C148.2 C149.1 C150.1 C151.1 C160.2 C161.2 C164.2 C165.1 C167.2 C168.2 C169.2 C170.2 C171.2 C172.2 C174.2 C175.2 C176.2 C182.1 C188.1 C190.2 C192.2 C197.2 C201.2 C202.2 C203.1 C205.1 C207.2 C208.2 C209.1 C213.1 C215.1 C216.1 C217.1 C221.2 C222.2 C223.1 C224.2 C225.1 C226.2 C227.2 C228.2 C229.2 C231.1 C232.2 C233.2 C234.2 C235.1 C236.1 C240.2 C241.2 C242.2 C244.2 C245.2 C246.2 C247.1 C248.2 C249.2 C250.2 C251.1 C254.2 C255.2 C256.2 C257.2 C258.2 C259.2 C260.2 C261.2 C262.1 C263.2 C264.1 C265.2 C266.1 C267.2 C269.2 C270.2 C271.2 C272.2 C273.2 C274.2 C275.1 C276.2 C277.2 C278.2 C279.2 C280.1 C281.1 C282.1 C283.1 C284.1 C285.2 C286.1 C287.1 C288.1 C289.1 C290.2 C291.1 C292.2 C293.2 C295.2 C300.1 C301.2 C302.2 C303.2 C305.2 C306.2 C307.2 C308.2 C309.2 C310.2 C312.2 C319.1 C320.1 C321.2 C322.2 C323.2 C324.2 C325.2 C326.2 C327.2 C329.2 C330.2 C332.1 C334.1 C336.1 C338.1 C340.2 C341.1 C342.1 C343.1 C344.1 C349.2 C350.2 C351.2 C352.2 C353.2 C354.2 C355.2 C356.2 C357.2 C358.2 C359.2 C360.2 C361.2 C362.2 C363.2 C364.2 C365.2 C366.2 C367.2 C368.2 C369.2 C370.2 C371.2 C372.2 C373.2 C374.2 C378.2 C379.2 C382.2 C383.2 C384.2 C385.2 C386.2 C387.2 C388.2 C389.2 C390.2 C391.1 C393.1 C394.1 C395.2 C408.2 C409.1 C414.1 C415.1 C416.1 C417.2 C421.1 C427.2 C429.2 C430.1 C432.2 C434.2 C437.2 C440.2 C441.2 C443.2 C445.2 C446.2 C447.2 C448.2 C449.1 C451.2 C453.2 C454.2 C455.1 C460.2 C461.2 C462.2 C463.2 C465.2 C466.2 C467.2 C468.2 C469.1 C470.1 C471.2 C473.1 C477.2 C478.1 C483.2 C484.2 C485.2 C488.2 C489.1 C490.2 C493.2 C494.2 C495.2 C497.2 C498.2 C500.1 C501.2 C502.2 C503.2 C504.2 C505.2 C506.2 C508.2 C509.2 C511.1 C512.2 C514.2 C515.1 C516.1 C517.2 C518.2 C520.2 C521.2 C525.2 C527.2 C528.1 C529.1 C532.2 C533.2 C534.2 C535.2 C536.2 C537.2 C538.2 C546.2 C547.2 C555.2 C560.2 C561.2 C565.2 C572.2 C574.1 C575.1 C576.2 C592.2 C593.2 C598.2 C599.1 C602.2 C604.2 C605.1 C606.1 C607.1 C608.1 C609.1 C610.2 C611.2 C612.1 C613.1 C614.2 C616.2 C617.1 C618.1 C620.2 C622.1 C631.2 C641.2 C642.2 C643.2 C644.2 C646.2 C647.2 C648.2 C649.2 C650.2 C651.2 C652.2 C653.2 C654.2 C655.2 C657.2 C658.2 C659.2 C660.2 C662.2 C663.2 C787.2 C3497.2 C3625.2 C3627.1 C3628.2 C3629.2 C3630.2 C3631.2 C3636.2 C3637.2 C3638.2 C3642.2 C3643.2 C3644.1 C3645.2 C3647.2 C3649.2 C3652.2 C3653.2 C3655.2 C3656.2 C3657.1 C3658.2 C3659.2 C3660.2 C3661.2 C3692.1 C3694.2 C3695.1 C3696.2 C3697.1 C3698.2 C3701.2 C3702.2 C3703.2 C3704.1 C3705.2 C3706.1 C3707.2 C3708.2 C3709.2 C3710.2 C3711.2 C3712.2 C3713.2 C3714.2 C3715.2 C3716.2 C3717.2 C3718.2 C3719.2 C3720.1 C3721.1 C3724.1 C3725.1 C3726.1 C3727.1 C3728.1 C3729.1 C3730.1 C3731.2 C3732.1 C3733.2 C3738.2 C3740.1 C3741.1 C3744.2 C3745.1 C3746.1 C3747.2 C3750.1 C3751.2 C3752.2 C3753.2 C3754.2 C3755.2 C3756.2 C3757.2 C3758.2 C3759.2 C3760.2 C3762.2 C3764.2 C3767.2 C3768.1 C3769.1 C3771.1 C3772.1 C3773.2 C3774.1 C3775.1 C3779.1 C3780.1 C3781.2 D1.1 D2.1 D3.1 D6.1 D7.2 D8.2 D9.1 D11.1 D12.1 D13.1 D14.1 D16.2 D17.2 D18.1 J1.1A J1.1B J2.1A J2.1B J3.1A J3.1B J4.1A J4.1B J7.2 J9.2 J12.7 J12.8 J12.15 J12.16 J12.22 J12.25 J12.26 J12.31 J12.35 J12.36 J12.45 J12.46 J12.49 J12.50 J12.57 J12.58 J12.65 J12.66 J12.75 J12.76 J12.81 J12.82 J12.83 J12.84 J12.85 J12.86 J12.87 J12.88(GND8) J13.7 J13.8 J13.15 J13.16 J13.22 J13.25 J13.26 J13.31 J13.35 J13.36 J13.45 J13.46 J13.49 J13.50 J13.57 J13.58 J13.65 J13.66 J13.75 J13.76 J13.81 J13.82 J13.83 J13.84 J13.85 J13.86 J13.87 J13.88(GND8) J14.10 J14.12 J14.16 J14.20 J16.2 J17.5 J18.1 J18.5 J18.8 J18.15 J18.16 J18.17 J18.18 J18.21 J18.24 J18.31 J18.32 J18.33 J18.34 J18.41 J19.1 J19.5 J19.8 J19.15 J19.16 J19.17 J19.18 J19.21 J19.24 J19.31 J19.32 J19.33 J19.34 J19.41 J21.2 J21.10 J22.5 J24.A1 J24.A12 J24.B1 J24.B12 J25.A1 J25.A12 J25.B1 J25.B12 J26.6(VSS) J26.SH1 J26.SH2 J26.SH3 J26.SH4 J31.12 J32.2 J33.2 J34.2 LD3.1(CATHODE) LD5.1(CATHODE) LD6.1(CATHODE) LD9.1(CATHODE) LD13.1(CATHODE) Q1.4 Q1.7(S2) Q2.2(EMITTER) Q3.2(S) Q5.4 Q5.7(S2) Q7.3 Q10.4 Q10.7(S2) Q12.3 R22.2 R26.2 R27.2 R30.2 R31.2 R32.2 R36.1 R37.1 R61.2 R63.2 R68.1 R76.2 R85.2 R94.2 R107.2 R112.1 R143.2 R145.2 R146.2 R147.2 R148.2 R149.2 R150.2 R151.2 R152.2 R153.2 R154.2 R155.2 R156.2 R157.2 R158.2 R159.2 R160.2 R202.2 R203.1 R214.1 R217.1 R218.2 R229.1 R230.1 R231.1 R232.1 R238.2 R254.1 R258.2 R278.1 R289.2 R303.2 R313.2 R320.2 R341.1 R355.1 R367.2 R373.2 R381.2 R385.1 R403.2 R404.2 R415.1 R418.1 R422.1 R429.2 R430.2 R438.1 R442.1 R451.2 R456.2 R489.1 R490.1 R504.2 R531.1 R545.2 R553.2 R555.1 R556.2 R560.2 R561.2 R562.2 R564.2 R569.1 R591.1 R606.2 R607.2 R609.1 R610.1 R613.1 R618.1 R622.1 R623.1 R624.1 R626.1 R628.1 R632.2 R635.1 R639.1 R642.1 R662.2 R672.2 R681.2 R682.2 R3651.2 R3652.2 R3724.2 R3727.1 R3736.2 R5216.1 R5681.2 R5709.2 R5728.2 R5733.2 R5745.1 R5754.1 R5760.1 R5766.2 R5767.2 R5773.2 R5789.2 R5799.1 R5800.1 R5806.2 R5820.1 R5821.1 R5822.2 R5823.1 R5829.1 R5830.2 R5833.2 SW5.1 SW5.4 SW6.1 SW6.4 SW7.1 SW7.4 SW8.1 SW8.4 SW10.1 SW10.4 TP1.1(TP) TP2.1(TP) TP40.1(TP) TP41.1(TP) TP42.1(TP) TP44.1(TP) TP77.1(TP) TP85.1(TP) TP106.1(TP) U2.2 U4.2 U5.25 U5.A1 U5.A2 U5.A3 U5.A4(VSS#A4) U6.25 U6.A1 U6.A2 U6.A3 U6.A4(VSS#A4) U7.8 U7.33(VSS) U8.8 U8.33(VSS) U10.5 U11.2 U12.4 U14.3 U15.25 U15.A1 U15.A2 U15.A3 U15.A4 U18.9 U18.25 U21.25 U21.33 U23.3 U25.4 U26.3 U27.3 U28.B3 U28.C1 U28.E5(VSSQ#E5) U29.5 U39.4 U40.7 U41.1 U43.2 U46.2 U48.10 U48.17 U48.48 U48.55 U48.58 U48.64 U48.66 U48.80 U48.114 U49.A6 U49.C4 U49.E7 U49.G5 U49.H10 U49.J5 U49.K8 U49.N2 U49.N5 U49.P4 U49.P6(VSSQ#P6) U51.4 U54.2 U55.6 U55.9(PAD) U56.5 U56.14 U56.32 U57.43 U59.4 U59.9 U60.3 U61.5(VSS) U62.2 U64.1 U64.5 U64.10 U64.11 U64.13 U64.15 U64.25 U64.35 U64.47 U64.51 U65.4 U66.3 U66.7 U67.4 U68.2 U69.4 U71.3 U73.4 U73.7 U75.3 U76.25 U76.A1 U76.A2 U76.A3 U76.A4(VSS#A4) U77.25 U77.A1 U77.A2 U77.A3 U77.A4(VSS#A4) U81.11 U81.12 U81.13 U81.25 U82.25 U82.33 U83.11 U83.12 U83.13 U83.25 U86.2 U87.3 U88.3 U90.3 U90.5 U90.6 U91.7 U92.C1 U93.3 U97.10 U97.11 U98.4 U102.4 U107.4 U109.3 U109.5 U109.6 U110.10 U110.11 U113.B3 U113.C1 U113.C3 U114.1 U114.2 U114.7 U115.C1 U115.C3 U116.1 U116.7 U117.1 U117.10 U117.11 U117.16 U118.7 U119.C1 U120.2 U123.C1 U124.7 U125.7 U125.9 U125.10 U125.11 U125.12 U125.14 U126.1 U126.7 U126.9 U126.10 U126.11 U126.12 U126.14 U126.16 U127.4 U129.20 U129.51 U129.59 U132.1 U132.2 U132.3 U132.7 U133.1 U133.2 U133.3 U133.7 U134.3 U134.9 U134.11 U135.3 U135.7 U136.A1 U136.A19 U136.B2 U136.C3 U136.C19 U136.D1 U136.D3 U136.D4 U136.D8 U136.D11 U136.D14 U136.D19 U136.E5 U136.E9 U136.E10 U136.E11 U136.E12 U136.E14 U136.E15 U136.E17 U136.E18 U136.F4 U136.F10 U136.F11 U136.F14 U136.F15 U136.F16 U136.G4 U136.G6 U136.G8 U136.G9 U136.G12 U136.G13 U136.G15 U136.H3 U136.H6 U136.H11 U136.J7 U136.J11 U136.J13 U136.J15 U136.K8 U136.K11 U136.K12 U136.K15 U136.L5 U136.L7 U136.L9 U136.L10 U136.L13 U136.L14 U136.L15 U136.M5 U136.M8 U136.M12 U136.M15 U136.N5 U136.N6 U136.N7 U136.N9 U136.N13 U136.N14 U136.N15 U136.P5 U136.P6 U136.P14 U136.P15 U136.R5 U136.R6 U136.R7 U136.R10 U136.R12 U136.R13 U136.R14 U136.R15 U136.T5 U136.T8 U136.T9 U136.T10 U136.T16 U136.U4 U136.U5 U136.U8 U136.U10 U136.U17 U136.V4 U136.V10 U136.V18 U136.W1 U136.W3 U136.W6(VSS#W6) U136.W10 U136.W19 U140.B3 U140.C1 U140.E5(VSSQ#E5) U2345.11 U2346.3 U2347.4 U2348.3 U2349.3 U2349.8 U2350.3 U2350.8 U2351.3 U2352.3 U2353.1 U2353.7 U2353.9 U2353.10 U2353.11 U2353.12 U2353.14 U2353.16 U2355.3 U2356.3 U2357.5 U2358.4 U3068.2 U3070.3 U3072.8 U3072.19 U3072.38 U3072.49 U3076.2 U3077.7 U3078.1 U3078.7 U3079.1 U3079.7 U3080.C1 U3080.C3 U3081.C1 U3081.C3 U3083.5 U3084.4 U3086.3 U3087.3 U3088.3 U3091.3 U3091.5 U3091.6 Y1.2 Y1.4 Y3.2 Y3.4 Y5.2 Y5.4 Y8.2 Y8.4
DVDD1V8_ALERT: R305.1 U123.A3 U124.3
DVDD3V3_ALERT: R505.1 U91.3 U92.A3
DVDD3V3_N: R327.4 R539.2
DVDD3V3_P: R327.1 R540.2
VBAT_IN: C49.1 C55.1 C95.1 C100.1 J7.1 U7.21 U8.21
VBUS_TYPEC1: C321.1 C326.1 C327.1 C641.1 C643.1 C654.1 C655.1 D5.1 J24.A4 J24.A9 J24.B4 J24.B9(VBUS4) R3933.1 TP107.1(TP) U129.13 U133.4 U133.5 U133.6(IN3)
VBUS_TYPEC2: C325.1 C638.1 C642.1 C644.1 C646.1 C647.1 C649.1 C650.1 C652.1 C653.1 D5.2 J25.A4 J25.A9 J25.B4 J25.B9(VBUS4) Q8.4 Q8.7 R401.2 R402.1 R675.1 TP108.1(TP) U129.3 U132.4 U132.5 U132.6(IN3)
VCC1V8_CLKBUF: C265.1 C266.2 C284.2 C286.2 FL10.1 R329.2 R348.2 U62.4(VDD) U65.6
VCC1V8_SYS: C37.1 C72.1 C73.1 C75.1 C76.1 C101.1 C102.2 C126.2 C137.1 C138.1 C141.1 C142.1 C146.1 C148.1 C149.2 C151.2 C160.1 C161.1 C164.1 C167.1 C168.1 C242.1 C256.1 C257.1 C261.1 C371.1 C372.1 C373.1 C374.1 C388.1 C389.1 C390.1 C395.1 C408.1 C414.2 C421.2 C455.2 C470.2 C478.2 C503.1 C511.2 C514.1 C518.1 C528.2 C555.1 C593.1 C608.2 C617.2 C3701.1 C3703.1 C3704.2 C3705.1 C3706.2 C3707.1 C3708.1 C3709.1 C3718.1 C3719.1 C3721.2 C3725.2 C3726.2 C3728.2 C3729.2 C3733.1 C3769.2 C3773.1 C3774.2 C3775.2 C3779.2 J12.10 J12.12 J13.10 J13.12 J29.1 L6.2 R17.2 R18.2 R67.2 R69.1 R70.2 R75.1 R83.1 R97.2 R115.1 R117.1 R122.2 R123.2 R124.2 R166.1 R220.1 R225.1 R242.1 R259.1 R262.1 R263.1 R264.1 R266.1 R267.1 R268.1 R269.1 R270.1 R275.1 R288.1 R291.1 R301.1 R334.2 R361.1 R375.1 R419.2 R423.2 R443.2 R444.2 R445.2 R446.2 R447.2 R448.2 R449.2 R450.2 R452.2 R454.2 R464.1 R465.1 R480.1 R533.2 R534.2 R536.2 R550.1 R554.2 R559.1 R565.1 R575.1 R598.1 R603.1 R611.1 R612.1 R614.2 R615.1 R631.1 R636.2 R684.1 R685.1 R5213.2 R5684.2 R5693.2 R5698.2 R5699.2 R5710.2 R5711.2 R5712.2 R5713.2 R5714.2 R5715.2 R5716.2 R5717.2 R5744.2 R5746.2 R5753.2 R5761.1 R5795.1 R5796.1 R5797.1 R5798.1 R5808.2 R5810.2 R5837.1 R5845.1 U2.5 U5.6 U6.6 U11.3 U12.1(VCC) U21.27(VCCP) U21.31 U26.5 U27.5 U28.B4 U28.D1 U28.E4 U29.8(VCCB) U39.1 U43.5 U49.C6 U49.M4 U49.N4 U49.P3 U49.P5 U56.18 U56.26 U76.6 U77.6 U81.23 U81.24(VCCB2) U83.23 U83.24(VCCB2) U86.5 U90.1 U93.5 U97.3 U98.8(VCC) U102.1 U109.1 U110.3 U125.3 U126.3 U140.B4 U140.D1 U140.E4 U2345.2 U2346.8(VDD) U2347.8(V+) U2348.5 U2351.8(VDD) U2352.8(VDD) U2353.3 U2355.5 U2358.8 U3077.1 U3083.1 U3086.5 U3087.5 U3088.5 U3091.1
VCC1V8_SYS_N: R334.4 R335.2
VCC1V8_SYS_P: R331.2 R334.1
VCC1V8_SYS_SW: L6.1 U56.13
VCC1V8_TA: C136.1 C236.2 C391.2 C393.2 C394.2 C409.2 C529.2 R126.2 R127.2 R128.2 R129.2 R130.2 R131.2 R132.2 R133.2 R134.2 R135.2 R136.2 R137.2 R138.2 R139.2 R140.2 R141.2 R277.2 R285.1 R439.2 R457.2 R461.2 R507.1 R511.1 R513.1 R516.1 R524.1 R526.1 R578.1 R582.1 R583.1 R643.2 U23.5 U51.1 U81.1 U82.27(VCCP) U82.31 U83.1 U107.1
VCC2V5_PG: R637.1 U127.2
VCC3V3_XDS: C147.1 C192.1 C208.1 C221.1 C222.1 C231.2 C232.1 C234.1 C235.2 C241.1 C243.1 C430.2 C469.2 C473.2 C488.1 C500.2 C515.2 C3720.2 R118.1 R119.1 R236.1 R237.1 R241.1 R246.2 R280.1 R306.1 R510.1 R512.1 R515.1 R517.1 R519.1 R520.2 R521.2 R522.2 R523.2 R525.1 R549.2 R551.1 R552.1 TP68.1(TP) U25.8(VCCB) U40.14(VCC) U48.7 U48.8 U48.16 U48.26 U48.28 U48.39 U48.47 U48.51 U48.52 U48.69 U48.79 U48.90 U48.101 U48.113 U48.122 U51.8(VCCB) U55.3 U55.4 U97.2(VCCB) U102.8(VCCB) U107.8(VCCB) U109.8(VCCB) U2353.2(VCCB)
VCC_0V85: C3738.1 R5747.1 U56.25
VCC_1V8_FT4232: C263.1 C280.2 C281.2 C599.2 U64.12 U64.37 U64.49(VREGOUT) U64.64
VCC_1V8_IOVDD: C71.1 C74.1 C84.1 C85.1 C109.1 C340.1 R20.1 R23.1 R60.1 R62.1 R67.1 R78.2 R90.2 R413.2 R416.2 U7.27 U8.27 U14.5 U75.5
VCC_3V3_AVDD: C52.1 C53.2 C63.1 C68.1 C86.1 C90.1 C97.2 C98.1 FL2.2 L2.1 L3.1 U7.1 U7.3 U8.1 U8.3
VCC_3V3_FT4232: C262.2 C264.2 C275.2 C285.1 C288.2 C289.2 C575.2 C612.2 C618.2 FL17.2 FL18.2 LD7.2 R321.2 R328.2 R333.2 U61.8 U64.20 U64.31 U64.42 U64.50 U64.56 U66.1(OUT) U117.2(VCCB) U125.2(VCCB) U126.2(VCCB)
VCC_3V3_SYS: C28.1 C33.2 C99.1 C122.2 C140.1 C150.2 C165.2 C169.1 C258.1 C259.1 C260.1 C271.1 C274.1 C277.1 C279.1 C293.1 C415.2 C416.2 C427.1 C498.1 C504.1 C520.1 C525.1 C560.1 C592.1 C598.1 C602.1 C604.1 C787.1 C3659.1 C3660.1 C3698.1 C3724.2 C3727.2 C3730.2 C3732.2 C3762.1 C3764.1 C3768.2 FL1.1 FL2.1 FL23.2 J14.5 J18.44 J18.46 J19.44 J19.46 J29.3 L7.2 R56.1 R58.1 R98.2 R180.2 R211.1 R212.1 R260.2 R292.2 R324.2 R327.2 R342.1 R343.2 R344.1 R347.1 R351.2 R356.1 R360.1 R362.2 R363.2 R440.2 R482.1 R485.2 R597.2 R601.2 R602.2 R616.2 R620.2 R625.2 R629.2 R630.2 R638.2 R641.2 R645.1 R5215.1 R5687.2 R5688.2 R5735.2 R5741.1 R5742.1 R5759.2 R5764.2 R5777.1 R5824.1 R5825.1 R5843.1 U4.1 U11.7(VCCB) U18.21(VCCP) U18.23 U25.1 U29.1 U39.8(VCCB) U49.E6 U49.F5 U49.J10 U49.K9 U57.1 U57.17 U57.30(VCC#30) U68.5 U87.5 U88.5 U90.8(VCCB) U91.1 U91.6(VS) U92.B1(VS) U92.C3 U110.2(VCCB) U113.B1(VS) U114.6(VS) U115.B1(VS) U115.B3 U116.2 U116.6(VS) U118.2 U118.6(VS) U119.B1(VS) U119.B3 U120.5 U123.B1(VS) U123.B3 U123.C3 U124.1 U124.2 U124.6(VS) U2357.1(V+) U3072.17(VCC) U3077.14(VCCB) U3078.6(VS) U3079.6(VS) U3080.B1(VS) U3081.B1(VS) U3083.8(VCCB)
VCC_3V3_SYS_CLK_BUF: C3771.2 C3772.2 FL23.1 R5790.1 U3084.6
VCC_3V3_SYS_REG_SW: L7.1 U56.15
VCC_5V0: C128.1 C129.1 C130.1 C133.1 C134.1 C135.1 C170.1 C171.1 C172.1 C174.1 C175.1 C176.1 C197.1 C255.1 C317.1 C318.1 C546.1 C547.1 C561.1 C565.1 C572.1 C576.1 C620.1 C639.1 C3497.1 C3636.1 C3637.1 C3638.1 C3643.1 C3692.2 C3695.2 C3747.1 J12.2 J12.4 J12.6 J13.2 J13.4 J13.6 L24.2 Q9.4 Q9.7 R240.1 R543.1 R665.1 R676.1 R3661.1 R3720.1 R3725.1 R5774.1 TP103.1(TP) U46.1 U56.3 U56.12 U56.16 U56.20 U56.30 U56.34 U59.8 U127.6(VIN) U134.1 U135.6 U3068.3 U3076.1
VCC_5V0_PG: R3653.1 U54.3 U86.3 U134.5
VCC_CORE: C226.1 C227.1 C228.1 C229.1 C532.1 C533.1 C534.1 C535.1 C536.1 C537.1 L4.2 L5.2 R265.4 R5748.1
VCC_CORE_N: R265.2 R572.2
VCC_CORE_P: R265.3 R571.2
VDD_0V85_N: R581.1 R585.2
VDD_0V85_P: R581.4 R584.2
VDD_1V8_N: R311.2 R316.4
VDD_1V8_P: R310.2 R316.1
VDD_2V5: C272.1 C273.1 C276.1 C278.1 C614.1 C615.1 C616.1 J18.4 J18.6 J19.4 J19.6 L11.2 R634.1 R637.2 TP92.1(TP)
VDD_CANUART: C207.1 R255.1 R5786.3 U46.5(OUT)
VDD_CANUART_ALERT: R5778.1 U3078.3 U3080.A3
VDD_CANUART_N: R5780.2 R5786.1
VDD_CANUART_P: R5781.2 R5786.4
VDD_CORE: C441.1 C445.1 C448.1 C460.1 C462.1 C468.1 C477.1 C494.1 C657.1 C658.1 C659.1 C660.1 C662.1 C663.1 C3661.1 C3751.1 C3752.1 C3753.1 C3754.1 C3755.1 C3756.1 C3757.1 FL8.1 R265.1 R5828.1 TP53.1(TP) U136.G7 U136.G11 U136.G14 U136.H9 U136.H10 U136.H13 U136.J12 U136.K7 U136.K9 U136.K13 U136.L8 U136.L11 U136.L12 U136.M7 U136.M9 U136.M13 U136.P7 U136.P13
VDD_CORE_ALERT: R586.1 U113.A3 U114.3
VDD_CORE_N: C524.2 R572.1 U113.D1 U113.D2 U114.8 U114.9
VDD_CORE_P: C524.1 R571.1 U113.D3 U114.10
VDD_CORE_REG_SW1: L4.1 U56.33
VDD_CORE_REG_SW2: L5.1 U56.31
VDD_MMC0: C69.1 FL4.1 U4.5 U4.6(VOUT)
VDD_MMC0_SD: C88.2 C93.2 FL4.2 J26.4 TP21.1(TP)
VDDA1V8: C254.1 C290.1 FL10.2 R316.2 U56.19
VDDA_1V8: C202.1 C483.1 FL6.1 FL9.1 FL13.1 FL20.1 FL21.1 FL22.1 R316.3 SW11.1 TP79.1(TP)
VDDA_1V8_ALERT: R608.1 U118.3 U119.A3
VDDA_1V8_FB1: C463.1 C485.1 C501.1 FL13.2 U136.J9 U136.J10 U136.M11
VDDA_1V8_FB2: C467.1 C3656.1 FL6.2 U136.K5 U136.N11
VDDA_1V8_FB3: C3647.1 FL20.2 U136.H7
VDDA_1V8_FB4: C3649.1 FL21.2 U136.P10
VDDA_1V8_FB_OSC: C508.1 FL9.2 U136.F5
VDDA_1V8_N: C597.2 R311.1 U118.8 U118.9 U119.D1 U119.D2
VDDA_1V8_P: C597.1 R310.1 U118.10 U119.D3
VDDA_ADC0: C3652.1 FL22.2 U136.J5
VDDA_CORE_USB: C495.1 C497.1 C3767.1 FL8.2 U136.N10
VDDA_SYS_MON: C449.2 R543.2 R545.1 U136.H8
VDDC_1V2: C233.1 C240.1 C516.2 U48.87 U48.115
VDDIM: C521.1 C527.1 U49.C2
VDDR_CANUART: C3653.1 R3731.2 U136.E7
VDDR_CORE: C447.1 C465.1 C466.1 C490.1 C493.1 C505.1 C3758.1 C3759.1 C3760.1 R272.1 R581.2 TP60.1(TP) U136.G10 U136.H12 U136.J8 U136.K10 U136.M10 U136.M14 U136.N8 U136.N12
VDDR_CORE_0V85: R581.3 R5747.2 R5748.2
VDDR_CORE_ALERT: R596.1 U115.A3 U116.3
VDDR_CORE_N: C559.2 R585.1 U115.D1 U115.D2 U116.8 U116.9
VDDR_CORE_P: C559.1 R584.1 U115.D3 U116.10
VDDSHV_CANUART: C538.1 C574.2 C3644.2 C3694.1 C3696.1 C3731.1 C3740.2 C3780.2 R282.1 R318.2 R322.1 R326.1 R371.1 R590.2 R592.1 R593.1 R643.1 R3653.2 R3723.1 R3726.2 R5638.2 R5692.2 R5736.2 R5737.2 R5756.1 R5787.3 TP80.1(TP) U54.5 U117.3 U135.1 U2356.8(VDD) U3068.5 U3070.5 U3091.8(VCCB)
VDDSHV_CANUART_ALERT: R5782.1 U3079.3 U3081.A3
VDDSHV_CANUART_N: R5784.2 R5787.1
VDDSHV_CANUART_P: R5785.2 R5787.4
VDDSHV_CANUART_PG: C3642.1 R3726.1 U135.5(PG)
VDDSHV_SDIO: C103.2 C201.1 C246.1 R54.2 R55.2 R57.2 R64.2 R65.2 R66.2 R243.1 U10.10(VCC) U56.21
VINT_LDO: C249.1 TP74.1(TP) U56.7(VOUT_LDOVINT)
ADC0_AIN0: J31.1 R5720.2 U2349.1 U2349.10(NC4)
ADC0_AIN0_R: C3710.1 R5720.1 U136.F1
ADC0_AIN1: J31.3 R5721.2 U2349.2 U2349.9
ADC0_AIN1_R: C3711.1 R5721.1 U136.H1
ADC0_AIN2: J31.5 R5722.2 U2349.4 U2349.7
ADC0_AIN2_R: C3712.1 R5722.1 U136.K2
ADC0_AIN3: J31.7 R5723.2 U2349.5 U2349.6
ADC0_AIN3_R: C3713.1 R5723.1 U136.K1
ADC0_AIN4: J31.9 R5724.2 U2350.1 U2350.10(NC4)
ADC0_AIN4_R: C3714.1 R5724.1 U136.F2
ADC0_AIN5: J31.11 R5725.2 U2350.2 U2350.9
ADC0_AIN5_R: C3715.1 R5725.1 U136.G2
ADC0_AIN6: J31.4 R5726.2 U2350.4 U2350.7
ADC0_AIN6_R: C3716.1 R5726.1 U136.J1
ADC0_AIN7: J31.6 R5727.2 U2350.5 U2350.6
ADC0_AIN7_R: C3717.1 R5727.1 U136.J2
ADC0_EXT_TRIGGER: J31.8 U136.V2
ADC0_REFN: C3742.2 C3743.1 R5728.1 U136.H2
ADC0_REFP: C3742.1 C3743.2 SW11.2(COM) U136.G1
ADC0_REFP_HDR: C3744.1 C3745.2 J31.2 SW11.3
ADCIN1: R679.2 R681.1 U129.6
ADCIN2: R678.2 R682.1 U129.10
ADDR0_IO_EXP: R107.1 U21.26
ADDR1_IO_EXP: R94.1 U18.18
AEC1_GPIO0_0: J12.42 U136.A6
AEC1_GPIO0_1: J12.44 R5757.2
AEC1_REFCLK_SEL: R5797.2 U21.23 U2346.1
AEC1_REFCLKIN: J12.33 U2346.2
AEC1_REFCLKOUT: J12.47 U2346.9
AEC2_GPIO0_0: J13.42 U136.A9
AEC2_GPIO0_1: J13.44 U136.B8
AEC2_REFCLK_SEL: R5798.2 U21.24 U2346.5
AEC2_REFCLKIN: J13.33 U2346.4
AEC2_REFCLKOUT: J13.47 U2346.7
AUDIO_EXT_REFCLK0: R538.2 U2346.10
AUDIO_EXT_REFCLK1: R506.2 U2346.6
AUDIO_EXT_REFCLK1__R: R506.1 U136.T1
AUDIO_EXT_REFCLK2: R5686.1 R5689.1
AUDIO_EXT_REFCLK2_R: R5689.2 U136.V3
AUDIO_EXT_REFCLK2_S0: R5795.2 U21.21 U2347.6
AUDIO_EXT_REFCLK2_S1: R5796.2 U21.22 U2347.5
BOOTMODE0: RA6.1 U81.14
BOOTMODE1: RA2.1 U81.15
BOOTMODE2: RA5.1 U81.16
BOOTMODE3: RA2.2 U81.17
BOOTMODE4: RA2.3 U81.18
BOOTMODE5: RA6.4 U81.19
BOOTMODE6: RA7.4 U81.20
BOOTMODE7: RA5.3 U81.21
BOOTMODE8: RA5.2 U83.14
BOOTMODE9: RA2.4 U83.15
BOOTMODE10: RA5.4 U83.16
BOOTMODE11: RA7.1 U83.17
BOOTMODE12: RA6.3 U83.18
BOOTMODE13: RA6.2 U83.19
BOOTMODE14: RA7.2 U83.20
BOOTMODE15: RA7.3 U83.21
BOOTMODE_I2C_EN: R578.2 U107.5
BOOTMODE_I2C_SCL: R579.1 R583.2 TP71.1(TP) U82.29
BOOTMODE_I2C_SDA: R580.1 R582.2 TP45.1(TP) U82.30
BOOTMODEON: R112.2 U23.4(Y) U81.22 U83.22
BUF_BOOTMODE_I2C0_SCL: R119.2 U25.7 U48.82
BUF_BOOTMODE_I2C0_SDA: R118.2 U25.6 U48.81
BUF_BOOTMODE_I2C_SCL: R552.2 U48.49 U107.7
BUF_BOOTMODE_I2C_SDA: R551.2 U48.50 U107.6
BUF_TEST_GPIO1: R519.2 U40.1 U48.74
BUF_TEST_GPIO2: R280.2 U48.73 U51.7
BUF_TEST_GPIO3: R515.2 U40.3 U48.72
BUF_TEST_GPIO4: R510.2 U40.5 U48.71
BUF_TEST_PORZN: R512.2 U40.9 U48.77
BUF_TEST_POWERDOWN: R525.2 U40.13 U48.78
BUF_TEST_WARMRESETN: R517.2 U40.11 U48.76
CAN-FD_INH: R3028.2 TP585.1(TP) U3068.7
CAP_VDDS0: C454.1 U136.L6
CAP_VDDS1: C434.1 U136.F13
CAP_VDDS2: C446.1 U136.R11
CAP_VDDS3: C432.1 U136.H15
CAP_VDDS5: C443.1 U136.P8
CAP_VDDS_CANUART: C509.1 U136.E6
CAP_VDDS_MCU: C484.1 U136.E8
CDCE_CLKOUT_1: R89.1 U2347.3
CLKOUT0: R336.2 R337.2 U65.1
CLKOUT_OSC: R336.1 U62.3
CORE_CONFIG: R371.2 SW7.3 TP76.1(TP) U56.8
CPSW_ETH_INTN: R621.1 U3077.12
CPSW_ETH_INTN_1V8: R205.2 U3077.3
CPSW_RGMII1_BCLK: J18.48 U29.3
CPSW_RGMII1_BCLK_1V8: U29.6 U2347.2
CPSW_RGMII1_BRD_CONN_DET: J18.36 R355.2
CPSW_RGMII1_COL: J18.14 TP590.1(TP)
CPSW_RGMII1_CRS: J18.30 TP591.1(TP)
CPSW_RGMII1_ETH1_CLK: J18.28 R359.2
CPSW_RGMII1_MDC: J18.20 R338.2 R342.2
CPSW_RGMII1_MDIO: J18.22 R340.2 R343.1
CPSW_RGMII1_RD0: J18.23 U136.W11
CPSW_RGMII1_RD1: J18.25 U136.T11
CPSW_RGMII1_RD2: J18.27 U136.T12
CPSW_RGMII1_RD3: J18.29 U136.U12
CPSW_RGMII1_RESETN: J18.12 R373.1 R5824.2 U68.4(Y)
CPSW_RGMII1_RX_DV: J18.45 U136.V12
CPSW_RGMII1_RXC: J18.19 U136.W12
CPSW_RGMII1_TD0: J18.7 R530.2
CPSW_RGMII1_TD1: J18.9 R535.2
CPSW_RGMII1_TD2: J18.11 R537.2
CPSW_RGMII1_TD3: J18.13 R529.2
CPSW_RGMII1_TX_EN: J18.35 U136.T13
CPSW_RGMII1_TXC: J18.3 R239.2
CPSW_RGMII2_BCLK: J19.48 U29.2
CPSW_RGMII2_BCLK_1V8: U29.7 U2347.1
CPSW_RGMII2_BRD_CONN_DET: J19.36 R341.2
CPSW_RGMII2_COL: J19.14 TP588.1(TP)
CPSW_RGMII2_CRS: J19.30 TP589.1(TP)
CPSW_RGMII2_ETH2_CLK: J19.28 R358.2
CPSW_RGMII2_MDC: J19.20 R352.2 R356.2
CPSW_RGMII2_MDIO: J19.22 R345.2 R351.1
CPSW_RGMII2_RD0: J19.23 U136.U15
CPSW_RGMII2_RD1: J19.25 U136.V15
CPSW_RGMII2_RD2: J19.27 U136.W14
CPSW_RGMII2_RD3: J19.29 U136.T15
CPSW_RGMII2_RSTN: J19.12 R607.1 R5825.2 U120.4(Y)
CPSW_RGMII2_RX_DV: J19.45 U136.V14
CPSW_RGMII2_RXC: J19.19 U136.W15
CPSW_RGMII2_TD0: J19.7 R509.2
CPSW_RGMII2_TD1: J19.9 R518.2
CPSW_RGMII2_TD2: J19.11 R527.2
CPSW_RGMII2_TD3: J19.13 R528.2
CPSW_RGMII2_TX_EN: J19.35 U136.U16
CPSW_RGMII2_TXC: J19.3 R228.2
CPSW_RGMII2_TXC_R: R228.1 U136.W17
CPSW_RGMII_INTN: J18.10 R346.1 R620.1 R621.2
CPSW_RGMII_INTN_R: J19.10 R344.2 R346.2
CPSW_RGMII_TXC_R: R239.1 U136.V13
DEBOUNCE_GPIO_INT_MCU_SOC: C489.2 D11.2 Q7.2(S) R559.2 SW5.2 SW5.3 U98.3
DEBOUNCE_IORET_WAKE: C3741.2 D18.2 R5756.2 SW10.2 SW10.3 U3070.2
DEBOUNCE_MCU_RESETZ: C609.2 D12.2 Q12.2(S) R615.2 SW6.2 SW6.3 U98.1
DEBOUNCE_SOC_PORZ: C622.2 D14.2 R375.2 SW8.2 SW8.3 U98.6
DIR: R461.1 U81.2 U83.2
DRAIN1: U129.8 U129.15 U129.19 U129.58
DRAIN2: U129.7 U129.52 U129.56 U129.57
ECAP0_IN_APWM_OUT: J13.11 R5685.1
ECAP1_IN_APWM_OUT: J12.9 U136.P2
ECAP2_IN_APWM_OUT: J12.11 U136.R3
ECAP3_IN_APWM_OUT: J13.9 U136.P4
EEPROM_A1: R5745.2 U2358.2
EEPROM_A2: R5744.1 U2358.3
EEPROM_WP: J33.1 R5746.1 U2358.7(WP)
EMMC_CLK: R561.1 R565.2 U49.M6 U57.42
EMMC_CMD: R575.2 U49.M5 U57.22
EMMC_D0: R269.2 U49.A3 U57.37
EMMC_D1: R266.2 U49.A4 U57.35
EMMC_D2: R263.2 U49.A5 U57.28
EMMC_D3: R275.2 U49.B2 U57.40
EMMC_D4: R270.2 U49.B3 U57.24
EMMC_D5: R267.2 U49.B4 U57.26
EMMC_D6: R264.2 U49.B5 U57.33
EMMC_D7: R262.2 U49.B6 U57.31
EMMC_RSTN: R117.2 R5822.1 U26.4(Y) U49.K5
EN_VSYS_5V0: R3028.1 R3727.2 R5740.2 U134.7
EPWM0_A: J12.3 U136.T2
EPWM0_B: J12.5 U136.R2
EPWM1_A: J13.3 U136.R1
EXT_CLKOUT0: R170.1 R337.1
EXT_CLKOUT0_R: R170.2 R5685.2 R5788.2 U136.P1
EXT_VMON2_1: J18.2 TP95.1(TP)
EXT_VMON2_2: J19.2 TP94.1(TP)
FT4232_DO: R321.1 R323.2 U61.4
FT4232_EECLK: R328.1 U61.2 U64.62
FT4232_EECS: R333.1 U61.1 U64.63
FT4232_EEDATA: R323.1 U61.3 U64.61
FT4232_REF: R609.2 U64.6
FT4232_RESET: C282.2 R357.1 U64.14
FT4232_SOC_UART2_RX_3V3: U64.16 U125.13
FT4232_SOC_UART2_TX_3V3: U64.17 U125.15
FT4232_SOC_UART3_RX_3V3: U64.26 U126.13
FT4232_SOC_UART3_TX_3V3: U64.27 U126.15
FT4232_UART2_RXD_1V8: R612.2 U125.8 U2351.7
FT4232_UART2_TXD_1V8: R611.2 U125.6 U2351.9
FT4232_UART3_RXD_1V8: R361.2 TP97.1(TP) U126.8 U2352.7
FT4232_UART3_TXD_1V8: R631.2 TP117.1(TP) U126.6 U2352.9
FT4232_USB_DM: J22.2 U64.7 U67.5
FT4232_USB_DP: J22.3 U64.8 U67.3
FT4232_USB_VBUS: C287.2 C291.2 C295.1 D3.2 J22.1(VBUS) TP96.1(TP) U66.4 U66.6 U67.1(VCC)
FT4232_WKUP_UART0_CTSN_3V3: U64.40 U117.12
FT4232_WKUP_UART0_RTSN_3V3: U64.41 U117.14
FT4232_WKUP_UART0_RXD_3V3: U64.38 U117.13
FT4232_WKUP_UART0_TXD_3V3: U64.39 U117.15
FT_PWREN#: R330.1 U64.60
GPIO2_BUF_EN: R277.1 R278.2 U51.5
GPIO_CPSW1_RST: R364.1 U18.11
GPIO_CPSW2_RST: R604.1 U18.10
GPIO_EMMC_RSTN: R116.1 U21.9
GPIO_HYPERRAM_RSTN: R5697.1 U136.C12
GPIO_MCU_SOC: R546.1 R547.1 U98.5
GPIO_MCU_SOC_INTN: R546.2 U136.C8
GPIO_PCM1_RST: R84.1 U21.17
GPIO_PCM2_RST: R414.1 U21.19
HW/SW_CTRL_SEL: R83.2 R85.1 U15.23
HYPERBUS0_CK: R5694.1 R5754.2 U140.B2
HYPERBUS0_CK#: R5695.1 R5753.1 U140.B1
HYPERBUS0_CS#: R5693.1 R5696.1 U140.A3
HYPERBUS0_DQ0: R5715.1 RA8.1 U140.D3
HYPERBUS0_DQ1: R5716.1 RA8.2 U140.D2
HYPERBUS0_DQ2: R5712.1 RA8.4 U140.C4
HYPERBUS0_DQ3: R5710.1 RA8.3 U140.D4
HYPERBUS0_DQ4: R5717.1 RA9.1 U140.D5
HYPERBUS0_DQ5: R5714.1 RA9.4 U140.E3
HYPERBUS0_DQ6: R5713.1 RA9.2 U140.E2
HYPERBUS0_DQ7: R5711.1 RA9.3 U140.E1
HYPERBUS0_RST#: R5698.1 R5820.2 U140.A4 U2348.4(Y)
HYPERBUS0_RWDS: R5709.1 R5752.1 R5810.1 U136.B15
I2C0_SCL_1V8: C188.2 R234.2 R296.1 R598.2 U5.7 U6.7 U7.25 U8.25 U11.5 U15.12 U21.29 U76.7 U77.7 U2358.6
I2C0_SCL_1V8_RC: R234.1 U136.M3
I2C0_SDA_1V8: C182.2 R210.2 R294.1 R603.2 U5.8 U6.8 U7.26 U8.26 U11.4 U15.19 U21.30 U76.8 U77.8 U2358.5
I2C0_SDA_1V8_RC: R210.1 U136.N3
I2C3_SCL_1V8: J12.18 R465.2 U136.N1
I2C3_SDA_1V8: J12.20 R464.2 U136.L3
I2C5_SCL_1V8: J13.18 R685.2 U136.L4
I2C5_SDA_1V8: J13.20 R684.2 U136.M4
I2C_ADDR0_A0: J18.47 R641.1 R642.2
I2C_ADDR0_A2: J18.37 R638.1 R639.2
I2C_ADDR1_A0: J19.47 R628.2 R630.1
I2C_ADDR1_A2: J19.37 R626.2 R629.1
INA_ALERT: R305.2 R505.2 R586.2 R596.2 R597.1 R608.2 R5778.2 R5782.2 TP46.1(TP)
IO_EXP0_INTN: R108.2 R5761.2 U21.32
IO_EXP1_INTN: R98.1 U18.22
IO_EXP_ADDR: R456.1 U82.26
IO_EXP_TEST_LED: R441.1 U18.12
IO_MCAN0_EN: R5639.2 U21.10
IO_MCAN0_STB#: R102.2 R5692.1 U21.12
IORET_WAKE: U136.D7 U3070.4(Y)
JTAG_CTI_RTCK: J14.9 R476.1
JTAG_CTI_TCK: J14.11 R485.1 R487.1 U87.1 U88.1
JTAG_DIR: R569.2 U110.4 U110.5
JTAG_EMU0: J14.13 R211.2 U39.7
JTAG_EMU1: J14.14 R212.2 U39.6
JTAG_EMU_RSTN: J14.15 R482.2 U86.6
JTAG_TCK: R483.1 U110.14
JTAG_TDI: J14.3 U110.12
JTAG_TDIS: J14.4 R490.2
JTAG_TDO: J14.7 U90.7
JTAG_TMS: J14.1 U110.13
JTAG_TRST#: J14.2 R489.2 U110.15
LDO_1V8: C303.1 U129.35
LDO_3V3: C292.1 C300.2 C319.2 R195.1 R374.1 R378.1 R644.1 R646.1 R658.1 R660.1 R664.1 R678.1 R679.1 U69.8 U71.5 U129.9
LM61460_BOOT: C3494.1 R5805.2 U134.14
LM61460_FB: C3639.2 R3651.1 R3720.2 U134.4
LM61460_RT: R3652.1 U134.6
LM61460_SW: C3494.2 L24.1 U134.10
LM61460_VCC: C3627.2 U134.2
MCAN0_CAN_H: J9.3 R88.2 U3068.13
MCAN0_CAN_L: J9.1 R93.1 U3068.12
MCAN0_EN: R5638.1 R5639.1 U3068.6
MCAN0_FAULT#: R5637.1 U3068.8
